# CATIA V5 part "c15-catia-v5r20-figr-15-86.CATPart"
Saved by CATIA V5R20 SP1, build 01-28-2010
Part number: Part1
Bounding box of the stored display mesh (mm): x -48.593 to 48.593, y -32.466 to 32.466, z -4 to 1
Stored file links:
  D:\v5_r20\psrt_files_downloaded\c15\c15-catia-v5r20-figr-15-86.CATPart
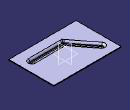
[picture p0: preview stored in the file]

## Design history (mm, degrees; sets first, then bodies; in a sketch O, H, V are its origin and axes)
SheetMetalParameters1: Thickness 1, BendRadius 5, KFactor 0.5 {= log(min(100,max(20*SheetMetalParameters1.BendRadius,SheetMetalParameters1.Thickness)/SheetMetalParameters1.Thickness))/log(100)/2}, ReliefRadialLength 1, ReliefAxialLength 2, MinimumBendRadius 0
Body1 (main body)
  Sketch1 on xy-plane, origin (0, 0, 0), H (1, 0, 0), V (0, 1, 0)
    line L1 (-48.5934, 32.4662) -> (48.5934, 32.4662)
    line L2 (48.5934, 32.4662) -> (48.5934, -32.4662)
    line L3 (48.5934, -32.4662) -> (-48.5934, -32.4662)
    line L4 (-48.5934, -32.4662) -> (-48.5934, 32.4662)
    horizontal: L1 H, L3 H
    vertical: L2 V, L4 V
    symmetry: L4 L2 V, L1 L3 H
  Wall1: Thickness 1, Profile Sketch1
  Sketch2 on face of Wall1, origin (0, 0, 1), H (1, 0, 0), V (0, 1, 0)
    line L1 (-36.124, 16.6928) -> (-12.1978, -14.1364)
    line L2 (-12.1978, -14.1364) -> (33.9455, -14.1364)
    point P3 (-12.1978, -14.1364)
    coincidence: P3 L1
    horizontal: L2 H
  d_Stamp1: Stamp_FilletRadius 2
